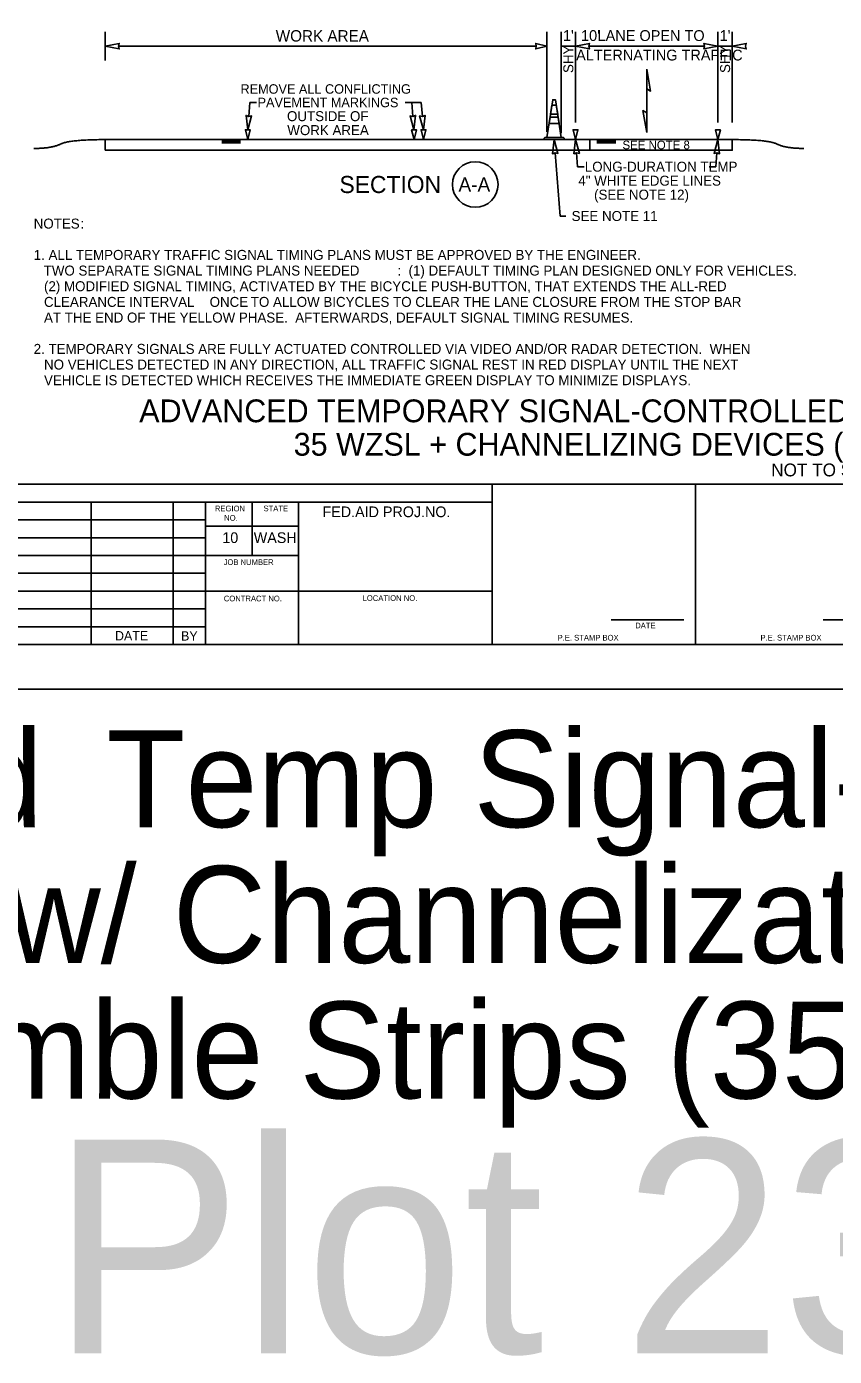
# Model space of a CAD drawing. Extents: x 99976 to 100136, y 99905 to 100011.
# Drawn here: x 100044.19 to 100049.86, y 99935.01 to 99944.34 of the extents above; entities that cross this region are included whole.
import ezdxf

# ---------------------------------------------------------------- set-up
doc = ezdxf.new("R2010")
doc.units = 0
for name, color, linetype in [('SH_DE_DetailHeading1Text', 7, 'Continuous'), ('SH_GI_GeneralNotesBodyText', 7, 'Continuous'), ('SH_GI_PlotLimits', 7, 'Continuous'), ('SH_GI_SheetBorder', 7, 'Continuous'), ('SH_GI_SheetLocationText', 7, 'Continuous'), ('SH_GI_SheetTextInCells', 7, 'Continuous'), ('TR_WZ_TrafficConeElev', 7, 'Continuous'), ('TR_WZ_WorkZoneDetails', 7, 'Continuous'), ('TR_WZ_WorkZoneTextCurrent', 7, 'Continuous')]:
    doc.layers.add(name, color=color, linetype=linetype)

msp = doc.modelspace()

# ---------------------------------------------------------------- linework, layer by layer
at = {"layer": 'SH_GI_PlotLimits'}
msp.add_lwpolyline([(100039.0625, 99939.6875), (100056.0625, 99939.6875), (100056.0625, 99950.6875), (100039.0625, 99950.6875)], close=True, dxfattribs=at)
at = {"layer": 'SH_GI_SheetBorder'}
for p, q in [((100040, 99941.1259), (100055.75, 99941.1259)), ((100047.4566, 99940), (100047.4566, 99941.1259)), ((100048.8828, 99940), (100048.8828, 99941.1259)), ((100040, 99941.0008), (100047.4566, 99941.0008)), ((100044.641, 99941.0008), (100044.641, 99940)), ((100045.2164, 99941.0008), (100045.2164, 99940)), ((100045.4451, 99941.0008), (100045.4451, 99940)), ((100045.7719, 99940.6255), (100045.7719, 99941.0008)), ((100046.0956, 99940), (100046.0956, 99941.0008)), ((100042.1821, 99940.8757), (100045.4466, 99940.8757)), ((100046.0958, 99940.831), (100045.4466, 99940.831)), ((100042.1821, 99940.7506), (100045.4466, 99940.7506)), ((100040, 99940.6255), (100045.4466, 99940.6255)), ((100046.0958, 99940.6255), (100045.4466, 99940.6255)), ((100040, 99940.5004), (100045.4466, 99940.5004)), ((100040, 99940.3753), (100045.4466, 99940.3753)), ((100047.4566, 99940.3753), (100045.4466, 99940.3753)), ((100040, 99940.2502), (100045.4466, 99940.2502)), ((100040, 99940.1251), (100045.4466, 99940.1251)), ((100048.2903, 99940.1733), (100048.802, 99940.1733)), ((100049.7797, 99940.1733), (100050.2914, 99940.1733)), ((100040, 99940), (100055.75, 99940))]:
    msp.add_line(p, q, dxfattribs=at)
at = {"layer": 'TR_WZ_TrafficConeElev'}
for p, q in [((100047.8754, 99943.7863), (100047.8655, 99943.7213)), ((100047.9057, 99943.7863), (100047.8754, 99943.7863)), ((100047.9156, 99943.7213), (100047.9057, 99943.7863)), ((100047.8624, 99943.7013), (100047.8555, 99943.6563)), ((100047.9187, 99943.7013), (100047.8624, 99943.7013)), ((100047.8655, 99943.7213), (100047.9156, 99943.7213)), ((100047.9256, 99943.6563), (100047.9187, 99943.7013)), ((100047.8555, 99943.6563), (100047.9256, 99943.6563)), ((100047.8262, 99943.5588), (100047.8212, 99943.5538)), ((100047.8212, 99943.5538), (100047.8212, 99943.5438)), ((100047.8212, 99943.5438), (100047.9599, 99943.5438)), ((100047.8405, 99943.5588), (100047.8262, 99943.5588)), ((100047.9599, 99943.5538), (100047.9549, 99943.5588)), ((100047.9599, 99943.5438), (100047.9599, 99943.5538))]:
    msp.add_line(p, q, dxfattribs=at)
msp.add_lwpolyline([(100047.8405, 99943.5588), (100047.9405, 99943.5588), (100047.8999, 99943.8238), (100047.8812, 99943.8238)], close=True, dxfattribs=at)
msp.add_lwpolyline([(100047.8405, 99943.5588), (100047.9405, 99943.5588), (100047.8999, 99943.8238), (100047.8812, 99943.8238)], close=True, dxfattribs=at)
msp.add_lwpolyline([(100047.9549, 99943.5588), (100047.9405, 99943.5588), (100047.8405, 99943.5588)], dxfattribs=at)
at = {"layer": 'TR_WZ_WorkZoneDetails'}
for p, q in [((100044.7405, 99944.0999), (100044.7405, 99944.2999)), ((100047.8405, 99943.5988), (100047.8405, 99944.2999)), ((100047.9405, 99943.5888), (100047.9405, 99944.2999)), ((100048.0405, 99943.6636), (100048.0405, 99944.2999)), ((100049.0405, 99943.6636), (100049.0405, 99944.2999)), ((100049.1405, 99943.6636), (100049.1405, 99944.2999)), ((100047.7656, 99944.1999), (100044.8342, 99944.1999)), ((100048.0405, 99944.1999), (100047.9405, 99944.1999)), ((100048.9468, 99944.1999), (100048.1343, 99944.1999)), ((100049.1405, 99944.1999), (100049.0405, 99944.1999)), ((100048.5405, 99943.9003), (100048.5405, 99943.7315)), ((100048.5405, 99943.7315), (100048.5405, 99943.9003)), ((100045.7479, 99943.7071), (100045.7557, 99943.8046)), ((100045.8018, 99943.8046), (100045.7557, 99943.8046)), ((100046.9586, 99943.8046), (100046.8458, 99943.8046)), ((100046.8997, 99943.7071), (100046.8919, 99943.8046)), ((100046.9664, 99943.7071), (100046.9586, 99943.8046)), ((100044.7405, 99943.5438), (100044.7405, 99943.4688)), ((100049.1405, 99943.5438), (100044.7405, 99943.5438)), ((100045.5575, 99943.5386), (100045.6905, 99943.5386)), ((100045.5575, 99943.533), (100045.6905, 99943.533)), ((100045.5575, 99943.5273), (100045.6905, 99943.5273)), ((100045.5575, 99943.5221), (100045.6905, 99943.5221)), ((100048.3235, 99943.5382), (100048.1905, 99943.5382)), ((100048.3235, 99943.5326), (100048.1905, 99943.5326)), ((100048.3235, 99943.5269), (100048.1905, 99943.5269)), ((100048.3235, 99943.5217), (100048.1905, 99943.5217)), ((100049.1405, 99943.5438), (100049.1405, 99943.4688)), ((100049.1405, 99943.4688), (100044.7405, 99943.4688)), ((100047.898, 99943.4504), (100047.9333, 99943.0068)), ((100048.048, 99943.4504), (100048.0557, 99943.3528)), ((100049.0331, 99943.4504), (100049.0253, 99943.3528)), ((100048.1019, 99943.3528), (100048.0557, 99943.3528)), ((100049.0253, 99943.3528), (100048.9792, 99943.3528)), ((100047.9733, 99943.0068), (100047.9333, 99943.0068))]:
    msp.add_line(p, q, dxfattribs=at)
for points in [[(100044.7405, 99944.1999), (100044.8388, 99944.1806), (100044.8342, 99944.1999), (100044.8388, 99944.2192)], [(100047.8405, 99944.1999), (100047.7619, 99944.1806), (100047.7656, 99944.1999), (100047.7619, 99944.2192)], [(100048.0405, 99944.1999), (100048.1388, 99944.1806), (100048.1343, 99944.1999), (100048.1388, 99944.2192)], [(100049.0405, 99944.1999), (100048.9423, 99944.1806), (100048.9468, 99944.1999), (100048.9423, 99944.2192)], [(100049.1405, 99944.1999), (100049.2388, 99944.1806), (100049.2343, 99944.1999), (100049.2388, 99944.2192)], [(100048.5405, 99944.0379), (100048.5675, 99943.8847), (100048.5405, 99943.9003)], [(100045.7405, 99943.6136), (100045.7674, 99943.7101), (100045.7479, 99943.7071), (100045.729, 99943.7131)], [(100046.9071, 99943.6136), (100046.8802, 99943.7101), (100046.8998, 99943.7071), (100046.9186, 99943.7131)], [(100046.9738, 99943.6136), (100046.9469, 99943.7101), (100046.9665, 99943.7071), (100046.9853, 99943.7131)], [(100048.5405, 99943.5939), (100048.5135, 99943.7471), (100048.5405, 99943.7315)], [(100045.7405, 99943.5438), (100045.7238, 99943.6136), (100045.7572, 99943.6136)], [(100046.9072, 99943.5438), (100046.8905, 99943.6136), (100046.9238, 99943.6136)], [(100046.9739, 99943.5438), (100046.9572, 99943.6136), (100046.9905, 99943.6136)], [(100048.0405, 99943.5438), (100048.0238, 99943.6136), (100048.0572, 99943.6136)], [(100049.0405, 99943.5438), (100049.0238, 99943.6136), (100049.0572, 99943.6136)], [(100047.8905, 99943.5438), (100047.9175, 99943.4474), (100047.8979, 99943.4504), (100047.8791, 99943.4443)], [(100048.0405, 99943.5438), (100048.0675, 99943.4474), (100048.0479, 99943.4504), (100048.0291, 99943.4443)], [(100048.1405, 99943.5438), (100049.1405, 99943.5438), (100049.1405, 99943.4688), (100048.1405, 99943.4688)], [(100048.1405, 99943.5438), (100049.1405, 99943.5438), (100049.1405, 99943.4688), (100048.1405, 99943.4688)], [(100049.0405, 99943.5438), (100049.0136, 99943.4474), (100049.0331, 99943.4504), (100049.052, 99943.4443)]]:
    msp.add_lwpolyline(points, close=True, dxfattribs=at)
for points in [[(100045.7572, 99943.6136), (100045.7238, 99943.6136), (100045.7405, 99943.5438), (100045.7572, 99943.6136)], [(100046.9238, 99943.6136), (100046.8905, 99943.6136), (100046.9072, 99943.5438), (100046.9238, 99943.6136)], [(100046.9905, 99943.6136), (100046.9572, 99943.6136), (100046.9739, 99943.5438), (100046.9905, 99943.6136)], [(100048.0572, 99943.6136), (100048.0238, 99943.6136), (100048.0405, 99943.5438), (100048.0572, 99943.6136)], [(100049.0572, 99943.6136), (100049.0238, 99943.6136), (100049.0405, 99943.5438), (100049.0572, 99943.6136)]]:
    msp.add_lwpolyline(points, dxfattribs=at)
msp.add_circle((100047.3371, 99943.2289), 0.16, dxfattribs=at)
for points in [[(100044.7405, 99943.5438), (100044.4893, 99943.5438), (100044.3639, 99943.4817), (100044.2384, 99943.4817)], [(100049.1405, 99943.5438), (100049.3917, 99943.544), (100049.5172, 99943.4819), (100049.6427, 99943.482)]]:
    msp.add_open_spline(points, degree=2, dxfattribs=at)

# ---------------------------------------------------------------- texts
at = {"layer": 'SH_DE_DetailHeading1Text'}
for s, height, p in [('ADVANCED TEMPORARY SIGNAL-CONTROLLED ALTERNATING 1-LANE, 2-WAY TRAFFIC', 0.16, (100044.9788, 99941.5606)), ('35 WZSL + CHANNELIZING DEVICES (35 MPH HIGHWAYS, 8+ DAYS)', 0.16, (100046.0628, 99941.3259)), ('NOT TO SCALE', 0.09, (100049.4141, 99941.1809))]:
    msp.add_text(s, height=height, rotation=360, dxfattribs=at).set_placement(p)
at = {"layer": 'SH_GI_GeneralNotesBodyText'}
for s, p in [('NOTES', (100044.2384, 99942.9196)), (':', (100044.5659, 99942.9196)), ('1. ALL TEMPORARY TRAFFIC SIGNAL TIMING PLANS MUST BE APPROVED BY THE ENGINEER.', (100044.2384, 99942.6998)), ('TWO SEPARATE SIGNAL TIMING PLANS NEEDED', (100044.3084, 99942.5899)), (':  (1) DEFAULT TIMING PLAN DESIGNED ONLY FOR VEHICLES. ', (100046.7909, 99942.5899)), ('(2) MODIFIED SIGNAL TIMING, ACTIVATED BY THE BICYCLE PUSH-BUTTON, THAT EXTENDS THE ALL-RED ', (100044.3106, 99942.48)), ('CLEARANCE INTERVAL ', (100044.3106, 99942.3701)), ('ONCE', (100045.4729, 99942.3701)), (' TO ALLOW BICYCLES TO CLEAR THE LANE CLOSURE FROM THE STOP BAR ', (100045.7357, 99942.3701)), ('AT THE END OF THE YELLOW PHASE.  AFTERWARDS, DEFAULT SIGNAL TIMING RESUMES.', (100044.3106, 99942.2602)), ('2. TEMPORARY SIGNALS ARE FULLY ACTUATED CONTROLLED VIA VIDEO AND/OR RADAR DETECTION.  WHEN ', (100044.2384, 99942.0404)), ('NO VEHICLES DETECTED IN ANY DIRECTION, ALL TRAFFIC SIGNAL REST IN RED DISPLAY UNTIL THE NEXT ', (100044.3106, 99941.9305)), ('VEHICLE IS DETECTED WHICH RECEIVES THE IMMEDIATE GREEN DISPLAY TO MINIMIZE DISPLAYS.', (100044.3106, 99941.8206))]:
    msp.add_text(s, height=0.07, rotation=360, dxfattribs=at).set_placement(p)
at = {"layer": 'SH_GI_SheetLocationText'}
for s, height, p in [('Advanced', 0.68, (100040.2607, 99938.7191)), (' Temp Signal-Controlled', 0.68, (100044.4951, 99938.7191)), ('Alt Traffic w/ Channelization Devices', 0.68, (100039.9592, 99937.7671)), ('& Rumble Strips (35 mph)', 0.68, (100041.8582, 99936.8151)), ('Plot 23', 1.5, (100044.3607, 99935.0267))]:
    msp.add_text(s, height=height, dxfattribs=at).set_placement(p)
at = {"layer": 'SH_GI_SheetTextInCells'}
for s, height, p in [('REGION', 0.04003, (100045.5099, 99940.9352)), ('STATE', 0.04003, (100045.8511, 99940.9357)), ('FED.AID PROJ.NO.', 0.07506, (100046.2652, 99940.8945)), ('NO.', 0.04003, (100045.5752, 99940.869)), ('10', 0.07506, (100045.5621, 99940.7131)), ('WASH', 0.07506, (100045.7826, 99940.7131)), ('JOB NUMBER', 0.04003, (100045.5712, 99940.5587)), ('CONTRACT NO.', 0.040032, (100045.5725, 99940.3037)), ('LOCATION NO.', 0.040032, (100046.5465, 99940.3067)), ('DATE', 0.04003, (100048.4597, 99940.1141)), ('DATE', 0.06505, (100044.8091, 99940.03)), ('BY', 0.06505, (100045.2725, 99940.0285)), ('P.E. STAMP BOX', 0.040032, (100047.915, 99940.0286)), ('P.E. STAMP BOX', 0.040032, (100049.339, 99940.0286))]:
    msp.add_text(s, height=height, dxfattribs=at).set_placement(p)
at = {"layer": 'TR_WZ_WorkZoneDetails'}
for s, height, p in [('WORK AREA', 0.08, (100045.937, 99944.2319)), ("10'", 0.076, (100048.0794, 99944.2359)), (' LANE OPEN TO', 0.076, (100048.1674, 99944.2359)), ("1'", 0.076, (100047.9525, 99944.2359)), ("1'", 0.076, (100049.0522, 99944.2359)), ('ALTERNATING TRAFFIC', 0.076, (100048.0449, 99944.0991))]:
    msp.add_text(s, height=height, dxfattribs=at).set_placement(p)
for s, height, rotation, p in [('SHY', 0.07, 90, (100048.0255, 99944.0112)), ('SHY', 0.07, 90, (100049.1255, 99944.0112)), ('SECTION', 0.12, 360, (100046.384, 99943.1689)), ('A-A', 0.1, 360, (100047.2192, 99943.1789))]:
    msp.add_text(s, height=height, rotation=rotation, dxfattribs=at).set_placement(p)
at = {"layer": 'TR_WZ_WorkZoneTextCurrent'}
for s, height, p in [('REMOVE ALL CONFLICTING', 0.0665, (100045.6895, 99943.8659)), ('PAVEMENT MARKINGS', 0.0665, (100045.8095, 99943.7714)), ('OUTSIDE OF', 0.07, (100046.016, 99943.6734)), ('WORK AREA', 0.07, (100046.018, 99943.5754)), ('SEE NOTE 8', 0.06, (100048.3705, 99943.4763)), ('LONG-DURATION TEMP', 0.07, (100048.1059, 99943.3188)), ('4" WHITE EDGE LINES', 0.07, (100048.0607, 99943.2208)), ('(SEE NOTE 12)', 0.07, (100048.171, 99943.1228)), ('SEE NOTE 11', 0.07, (100048.0133, 99942.9728))]:
    msp.add_text(s, height=height, dxfattribs=at).set_placement(p)

doc.saveas('drawing.dxf')
